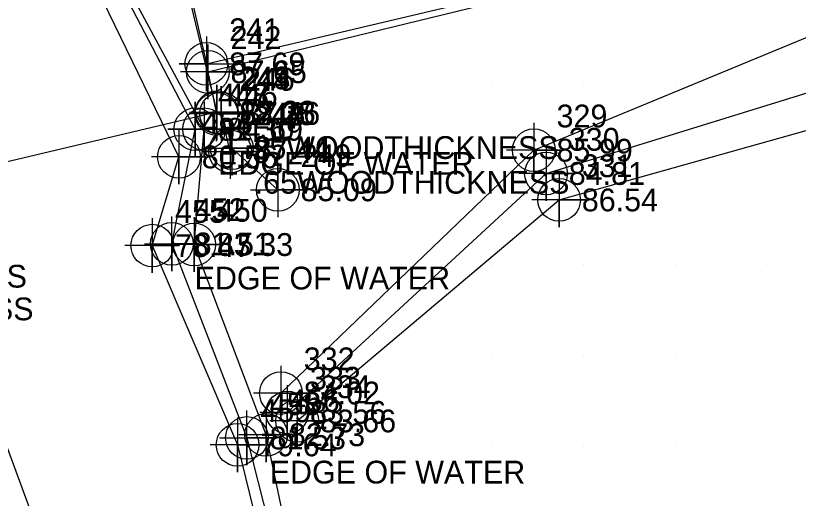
# Model space of a CAD drawing. Extents: x 1988140 to 1988766, y 249950 to 250250.
# Drawn here: x 1988457.6 to 1988543.5, y 250014.3 to 250067.3 of the extents above; entities that cross this region are included whole.
import ezdxf

# ---------------------------------------------------------------- set-up
doc = ezdxf.new("R2010")
doc.units = 0
for name, color, linetype in [('Exist DTM Breakline', 7, 'Continuous'), ('Exist DTM Breakline Cogo Elevation', 7, 'Continuous'), ('Exist DTM Breakline Cogo Number', 7, 'Continuous'), ('Exist DTM Breakline Cogo Point CELL', 7, 'Continuous'), ('Exist DTM Breakline Underwater', 7, 'Continuous'), ('Exist DTM QL2 LIDAR Elevation Point', 7, 'Continuous'), ('Exist Hydro Stream or Body of Water', 7, 'Continuous'), ('Exist Hydro Stream or Body of Water Cogo Comment', 7, 'Continuous'), ('Exist Hydro Stream or Body of Water Cogo Elevation', 7, 'Continuous'), ('Exist Hydro Stream or Body of Water Cogo Number', 7, 'Continuous'), ('Exist Hydro Stream or Body of Water Cogo Point CELL', 7, 'Continuous'), ('Exist Roads Change in Surface', 7, 'Continuous'), ('Exist Roads EOP', 7, 'Continuous'), ('Exist Roads EOP Cogo Elevation', 7, 'Continuous'), ('Exist Roads EOP Cogo Number', 7, 'Continuous'), ('Exist Roads EOP Cogo Point CELL', 7, 'Continuous'), ('Exist Roads EOT', 7, 'Continuous'), ('Exist Roads EOT Cogo Elevation', 7, 'Continuous'), ('Exist Roads EOT Cogo Number', 7, 'Continuous'), ('Exist Roads EOT Cogo Point CELL', 7, 'Continuous'), ('Exist Structure Major Bridge WW', 7, 'Continuous'), ('Exist Structure Major Deck Tunnel Box Culvert', 7, 'Continuous'), ('Exist Structure Major Deck Tunnel Box Culvert Cogo Elevation', 7, 'Continuous'), ('Exist Structure Major Deck Tunnel Box Culvert Cogo Number', 7, 'Continuous'), ('Exist Structure Major Deck Tunnel Box Culvert Cogo Point CELL', 7, 'Continuous'), ('Exist Structure Minor Head and End Wall Cogo Comment', 7, 'Continuous'), ('Exist Structure Minor Head and End Wall Cogo Elevation', 7, 'Continuous'), ('Exist Structure Minor Head and End Wall Cogo Number', 7, 'Continuous'), ('Exist Structure Minor Head and End Wall Cogo Point CELL', 7, 'Continuous')]:
    doc.layers.add(name, color=color, linetype=linetype)

msp = doc.modelspace()

# ---------------------------------------------------------------- linework, layer by layer
at = {"layer": 'Exist DTM Breakline'}
for p, q in [((1988514.4933, 250052.5489), (1988550.0675, 250067.2509)), ((1988515.8353, 250049.9896), (1988550.3151, 250060.6577)), ((1988517.2677, 250047.0884), (1988550.3991, 250056.4169)), ((1988486.7412, 250025.8932), (1988514.4933, 250052.5489)), ((1988487.4335, 250023.7691), (1988515.8353, 250049.9896)), ((1988488.5149, 250022.8285), (1988517.2677, 250047.0884))]:
    msp.add_line(p, q, dxfattribs=at)
msp.add_lwpolyline([(1988502.0577, 249958.2531), (1988491.6502, 249990.2233), (1988485.1148, 250021.3111), (1988477.2086, 250042.1909), (1988478.2961, 250054.8431), (1988462.5221, 250084.1865), (1988467.6761, 250104.4545), (1988466.937, 250133.0471)], dxfattribs=at)
at = {"layer": 'Exist DTM Breakline Cogo Point CELL'}
for points in [[(1988477.3409, 250057.8476), (1988477.3409, 250051.8476), (1988477.3409, 250054.8476), (1988480.3409, 250054.8476), (1988474.3409, 250054.8476)], [(1988478.2961, 250057.8431), (1988478.2961, 250051.8431), (1988478.2961, 250054.8431), (1988481.2961, 250054.8431), (1988475.2961, 250054.8431)], [(1988514.4933, 250055.5489), (1988514.4933, 250049.5489), (1988514.4933, 250052.5489), (1988517.4933, 250052.5489), (1988511.4933, 250052.5489)], [(1988475.5478, 250054.8121), (1988475.5478, 250048.8121), (1988475.5478, 250051.8121), (1988478.5478, 250051.8121), (1988472.5478, 250051.8121)], [(1988475.5478, 250054.8121), (1988475.5478, 250048.8121), (1988475.5478, 250051.8121), (1988478.5478, 250051.8121), (1988472.5478, 250051.8121)], [(1988515.8353, 250052.9896), (1988515.8353, 250046.9896), (1988515.8353, 250049.9896), (1988518.8353, 250049.9896), (1988512.8353, 250049.9896)], [(1988517.2677, 250050.0884), (1988517.2677, 250044.0884), (1988517.2677, 250047.0884), (1988520.2677, 250047.0884), (1988514.2677, 250047.0884)], [(1988472.6196, 250045.0736), (1988472.6196, 250039.0736), (1988472.6196, 250042.0736), (1988475.6196, 250042.0736), (1988469.6196, 250042.0736)], [(1988477.2086, 250045.1909), (1988477.2086, 250039.1909), (1988477.2086, 250042.1909), (1988480.2086, 250042.1909), (1988474.2086, 250042.1909)], [(1988486.7412, 250028.8932), (1988486.7412, 250022.8932), (1988486.7412, 250025.8932), (1988489.7412, 250025.8932), (1988483.7412, 250025.8932)], [(1988487.4335, 250026.7691), (1988487.4335, 250020.7691), (1988487.4335, 250023.7691), (1988490.4335, 250023.7691), (1988484.4335, 250023.7691)], [(1988488.5149, 250025.8285), (1988488.5149, 250019.8285), (1988488.5149, 250022.8285), (1988491.5149, 250022.8285), (1988485.5149, 250022.8285)], [(1988485.1148, 250024.3111), (1988485.1148, 250018.3111), (1988485.1148, 250021.3111), (1988488.1148, 250021.3111), (1988482.1148, 250021.3111)], [(1988481.9819, 250023.1998), (1988481.9819, 250017.1998), (1988481.9819, 250020.1998), (1988484.9819, 250020.1998), (1988478.9819, 250020.1998)]]:
    msp.add_lwpolyline(points, dxfattribs=at)
for centre in [(1988477.3409, 250054.8476), (1988478.2961, 250054.8431), (1988514.4933, 250052.5489), (1988475.5478, 250051.8121), (1988475.5478, 250051.8121), (1988515.8353, 250049.9896), (1988517.2677, 250047.0884), (1988472.6196, 250042.0736), (1988477.2086, 250042.1909), (1988486.7412, 250025.8932), (1988487.4335, 250023.7691), (1988488.5149, 250022.8285), (1988485.1148, 250021.3111), (1988481.9819, 250020.1998)]:
    msp.add_circle(centre, 2.344, dxfattribs=at)
at = {"layer": 'Exist DTM Breakline Underwater'}
for points in [[(1988472.6196, 250042.0736), (1988475.5478, 250051.8121), (1988460.2177, 250083.319), (1988463.5509, 250101.4082), (1988462.7669, 250131.4643), (1988448.9433, 250161.2866), (1988447.9748, 250187.7776)], [(1988432.5434, 250186.7094), (1988425.7037, 250133.7144), (1988438.98, 250078.1677), (1988446.627, 250047.162), (1988463.2661, 250001.9742), (1988462.1612, 249955.3502)], [(1988472.6196, 250042.0736), (1988481.9819, 250020.1998), (1988489.4621, 249989.5681), (1988498.0052, 249957.771)]]:
    msp.add_lwpolyline(points, dxfattribs=at)
at = {"layer": 'Exist DTM QL2 LIDAR Elevation Point'}
for p, q in [((1988490, 250060), (1988490, 250060)), ((1988500, 250060), (1988500, 250060)), ((1988510, 250060), (1988510, 250060)), ((1988520, 250060), (1988520, 250060)), ((1988530, 250060), (1988530, 250060)), ((1988490, 250050), (1988490, 250050)), ((1988500, 250050), (1988500, 250050)), ((1988510, 250050), (1988510, 250050)), ((1988530, 250050), (1988530, 250050)), ((1988540, 250050), (1988540, 250050)), ((1988480, 250040), (1988480, 250040)), ((1988490, 250040), (1988490, 250040)), ((1988500, 250040), (1988500, 250040)), ((1988510, 250040), (1988510, 250040)), ((1988520, 250040), (1988520, 250040)), ((1988530, 250040), (1988530, 250040)), ((1988540, 250040), (1988540, 250040)), ((1988490, 250030), (1988490, 250030)), ((1988500, 250030), (1988500, 250030)), ((1988510, 250030), (1988510, 250030)), ((1988520, 250030), (1988520, 250030)), ((1988530, 250030), (1988530, 250030)), ((1988540, 250030), (1988540, 250030)), ((1988490, 250020), (1988490, 250020)), ((1988500, 250020), (1988500, 250020)), ((1988510, 250020), (1988510, 250020)), ((1988520, 250020), (1988520, 250020)), ((1988530, 250020), (1988530, 250020)), ((1988540, 250020), (1988540, 250020))]:
    msp.add_line(p, q, dxfattribs=at)
at = {"layer": 'Exist Hydro Stream or Body of Water'}
for points in [[(1988474.7634, 250042.2609), (1988477.3409, 250054.8476), (1988462.0354, 250084.1709), (1988466.3899, 250102.3572), (1988465.3709, 250132.3106), (1988450.4249, 250163.1283), (1988449.3573, 250188.3896)], [(1988474.7634, 250042.2609), (1988483.0043, 250020.9618), (1988490.779, 249990.2887), (1988500.1927, 249958.0481)]]:
    msp.add_lwpolyline(points, dxfattribs=at)
at = {"layer": 'Exist Hydro Stream or Body of Water Cogo Point CELL'}
for points in [[(1988474.3409, 250054.8476), (1988480.3409, 250054.8476), (1988477.3409, 250054.8476), (1988477.3409, 250051.8476), (1988477.3409, 250057.8476)], [(1988471.7634, 250042.2609), (1988477.7634, 250042.2609), (1988474.7634, 250042.2609), (1988474.7634, 250039.2609), (1988474.7634, 250045.2609)], [(1988480.0043, 250020.9618), (1988486.0043, 250020.9618), (1988483.0043, 250020.9618), (1988483.0043, 250017.9618), (1988483.0043, 250023.9618)]]:
    msp.add_lwpolyline(points, dxfattribs=at)
for centre in [(1988477.3409, 250054.8476), (1988474.7634, 250042.2609), (1988483.0043, 250020.9618)]:
    msp.add_circle(centre, 2.344, dxfattribs=at)
at = {"layer": 'Exist Roads Change in Surface'}
msp.add_lwpolyline([(1988472.9466, 250084.7703), (1988474.5186, 250079.1384), (1988474.7146, 250078.1173), (1988476.6655, 250070.3758), (1988478.5507, 250062.0221), (1988478.7113, 250061.1525), (1988479.6615, 250056.5423)], dxfattribs=at)
at = {"layer": 'Exist Roads EOP'}
msp.add_lwpolyline([(1988478.7113, 250061.1525), (1988526.3961, 250072.7689), (1988588.4517, 250087.5135), (1988658.4677, 250104.3569), (1988725.1723, 250119.8591), (1988750.1331, 250125.8579)], dxfattribs=at)
at = {"layer": 'Exist Roads EOP Cogo Point CELL'}
for points in [[(1988478.7113, 250064.1525), (1988478.7113, 250058.1525), (1988478.7113, 250061.1525), (1988481.7113, 250061.1525), (1988475.7113, 250061.1525)], [(1988479.6615, 250059.5423), (1988479.6615, 250053.5423), (1988479.6615, 250056.5423), (1988482.6615, 250056.5423), (1988476.6615, 250056.5423)]]:
    msp.add_lwpolyline(points, dxfattribs=at)
for centre in [(1988478.7113, 250061.1525), (1988479.6615, 250056.5423)]:
    msp.add_circle(centre, 2.344, dxfattribs=at)
at = {"layer": 'Exist Roads EOT'}
msp.add_lwpolyline([(1988478.5507, 250062.0221), (1988526.3466, 250073.3488), (1988588.4376, 250088.1415), (1988658.1757, 250104.9714), (1988725.0188, 250120.3526), (1988749.8922, 250126.2558)], dxfattribs=at)
at = {"layer": 'Exist Roads EOT Cogo Point CELL'}
msp.add_lwpolyline([(1988478.5507, 250065.0221), (1988478.5507, 250059.0221), (1988478.5507, 250062.0221), (1988475.5507, 250062.0221), (1988481.5507, 250062.0221)], dxfattribs=at)
msp.add_circle((1988478.5507, 250062.0221), 2.344, dxfattribs=at)
at = {"layer": 'Exist Structure Major Bridge WW'}
for p, q in [((1988481.1651, 250052.3937), (1988480.1771, 250056.5858)), ((1988486.4002, 250048.1956), (1988481.3568, 250052.7719))]:
    msp.add_line(p, q, dxfattribs=at)
at = {"layer": 'Exist Structure Major Deck Tunnel Box Culvert'}
msp.add_lwpolyline([(1988414.7923, 250071.0539), (1988472.9466, 250084.7703), (1988479.6979, 250056.7161), (1988421.5011, 250042.945)], close=True, dxfattribs=at)
at = {"layer": 'Exist Structure Major Deck Tunnel Box Culvert Cogo Point CELL'}
msp.add_lwpolyline([(1988476.6979, 250056.7161), (1988482.6979, 250056.7161), (1988479.6979, 250056.7161), (1988479.6979, 250059.7161), (1988479.6979, 250053.7161)], dxfattribs=at)
msp.add_circle((1988479.6979, 250056.7161), 2.344, dxfattribs=at)
at = {"layer": 'Exist Structure Minor Head and End Wall Cogo Point CELL'}
for points in [[(1988477.1771, 250056.5858), (1988483.1771, 250056.5858), (1988480.1771, 250056.5858), (1988480.1771, 250059.5858), (1988480.1771, 250053.5858)], [(1988478.1651, 250052.3937), (1988484.1651, 250052.3937), (1988481.1651, 250052.3937), (1988481.1651, 250055.3937), (1988481.1651, 250049.3937)], [(1988478.3568, 250052.7719), (1988484.3568, 250052.7719), (1988481.3568, 250052.7719), (1988481.3568, 250055.7719), (1988481.3568, 250049.7719)], [(1988483.4002, 250048.1956), (1988489.4002, 250048.1956), (1988486.4002, 250048.1956), (1988486.4002, 250051.1956), (1988486.4002, 250045.1956)]]:
    msp.add_lwpolyline(points, dxfattribs=at)
for centre in [(1988480.1771, 250056.5858), (1988481.1651, 250052.3937), (1988481.3568, 250052.7719), (1988486.4002, 250048.1956)]:
    msp.add_circle(centre, 2.344, dxfattribs=at)

# ---------------------------------------------------------------- texts
at = {"layer": 'Exist DTM Breakline Cogo Elevation'}
for s, p in [('81.30', (1988479.8409, 250053.5976)), ('84.69', (1988480.7961, 250053.5931)), ('85.99', (1988516.9933, 250051.2989)), ('80.56', (1988478.0478, 250050.5621)), ('80.56', (1988478.0478, 250050.5621)), ('84.81', (1988518.3353, 250048.7396)), ('86.54', (1988519.7677, 250045.8384)), ('78.47', (1988475.1196, 250040.8236)), ('83.33', (1988479.7086, 250040.9409)), ('84.02', (1988489.2412, 250024.6432)), ('83.56', (1988489.9335, 250022.5191)), ('83.66', (1988491.0149, 250021.5785)), ('82.73', (1988487.6148, 250020.0611)), ('79.64', (1988484.4819, 250018.9498))]:
    msp.add_text(s, height=2.5, dxfattribs=at).set_placement(p)
at = {"layer": 'Exist DTM Breakline Cogo Number'}
for s, p in [('447', (1988479.8409, 250057.3476)), ('446', (1988480.7961, 250057.3431)), ('329', (1988516.9933, 250055.0489)), ('453', (1988478.0478, 250054.3121)), ('454', (1988478.0478, 250054.3121)), ('330', (1988518.3353, 250052.4896)), ('331', (1988519.7677, 250049.5884)), ('455', (1988475.1196, 250044.5736)), ('450', (1988479.7086, 250044.6909)), ('332', (1988489.2412, 250028.3932)), ('333', (1988489.9335, 250026.2691)), ('334', (1988491.0149, 250025.3285)), ('456', (1988487.6148, 250023.8111)), ('459', (1988484.4819, 250022.6998))]:
    msp.add_text(s, height=2.5, dxfattribs=at).set_placement(p)
at = {"layer": 'Exist Hydro Stream or Body of Water Cogo Comment'}
for p in [(1988479.8409, 250049.8476), (1988477.2634, 250037.2609), (1988485.5043, 250015.9618)]:
    msp.add_text('EDGE OF WATER', height=2.5, dxfattribs=at).set_placement(p)
at = {"layer": 'Exist Hydro Stream or Body of Water Cogo Elevation'}
for s, p in [('81.30', (1988479.8409, 250053.5976)), ('81.51', (1988477.2634, 250041.0109)), ('81.53', (1988485.5043, 250019.7118))]:
    msp.add_text(s, height=2.5, dxfattribs=at).set_placement(p)
at = {"layer": 'Exist Hydro Stream or Body of Water Cogo Number'}
for s, p in [('448', (1988479.8409, 250057.3476)), ('452', (1988477.2634, 250044.7609)), ('458', (1988485.5043, 250023.4618))]:
    msp.add_text(s, height=2.5, dxfattribs=at).set_placement(p)
at = {"layer": 'Exist Roads EOP Cogo Elevation'}
for s, p in [('87.65', (1988481.2113, 250059.9025)), ('88.25', (1988482.1615, 250055.2923))]:
    msp.add_text(s, height=2.5, dxfattribs=at).set_placement(p)
at = {"layer": 'Exist Roads EOP Cogo Number'}
for s, p in [('242', (1988481.2113, 250063.6525)), ('244', (1988482.1615, 250059.0423))]:
    msp.add_text(s, height=2.5, dxfattribs=at).set_placement(p)
at = {"layer": 'Exist Roads EOT Cogo Elevation'}
msp.add_text('87.69', height=2.5, dxfattribs=at).set_placement((1988481.0507, 250060.7721))
at = {"layer": 'Exist Roads EOT Cogo Number'}
msp.add_text('241', height=2.5, dxfattribs=at).set_placement((1988481.0507, 250064.5221))
at = {"layer": 'Exist Structure Major Deck Tunnel Box Culvert Cogo Elevation'}
msp.add_text('87.38', height=2.5, dxfattribs=at).set_placement((1988482.1979, 250055.4661))
at = {"layer": 'Exist Structure Major Deck Tunnel Box Culvert Cogo Number'}
msp.add_text('243', height=2.5, dxfattribs=at).set_placement((1988482.1979, 250059.2161))
at = {"layer": 'Exist Structure Minor Head and End Wall Cogo Comment'}
for s, p in [('.25WOODTHICKNESS', (1988482.6771, 250051.5858)), ('.65WOODTHICKNESS', (1988483.8568, 250047.7719)), ('.25WOOD THICKNESS', (1988423.3774, 250037.463)), ('.65WOOD THICKNESS', (1988424.0974, 250033.8772))]:
    msp.add_text(s, height=2.5, dxfattribs=at).set_placement(p)
at = {"layer": 'Exist Structure Minor Head and End Wall Cogo Elevation'}
for s, p in [('87.46', (1988482.6771, 250055.3358)), ('87.44', (1988483.6651, 250051.1437)), ('87.44', (1988483.8568, 250051.5219)), ('85.09', (1988488.9002, 250046.9456))]:
    msp.add_text(s, height=2.5, dxfattribs=at).set_placement(p)
at = {"layer": 'Exist Structure Minor Head and End Wall Cogo Number'}
for s, p in [('246', (1988482.6771, 250059.0858)), ('247', (1988483.6651, 250054.8937)), ('248', (1988483.8568, 250055.2719)), ('249', (1988488.9002, 250050.6956))]:
    msp.add_text(s, height=2.5, dxfattribs=at).set_placement(p)

doc.saveas('drawing.dxf')
